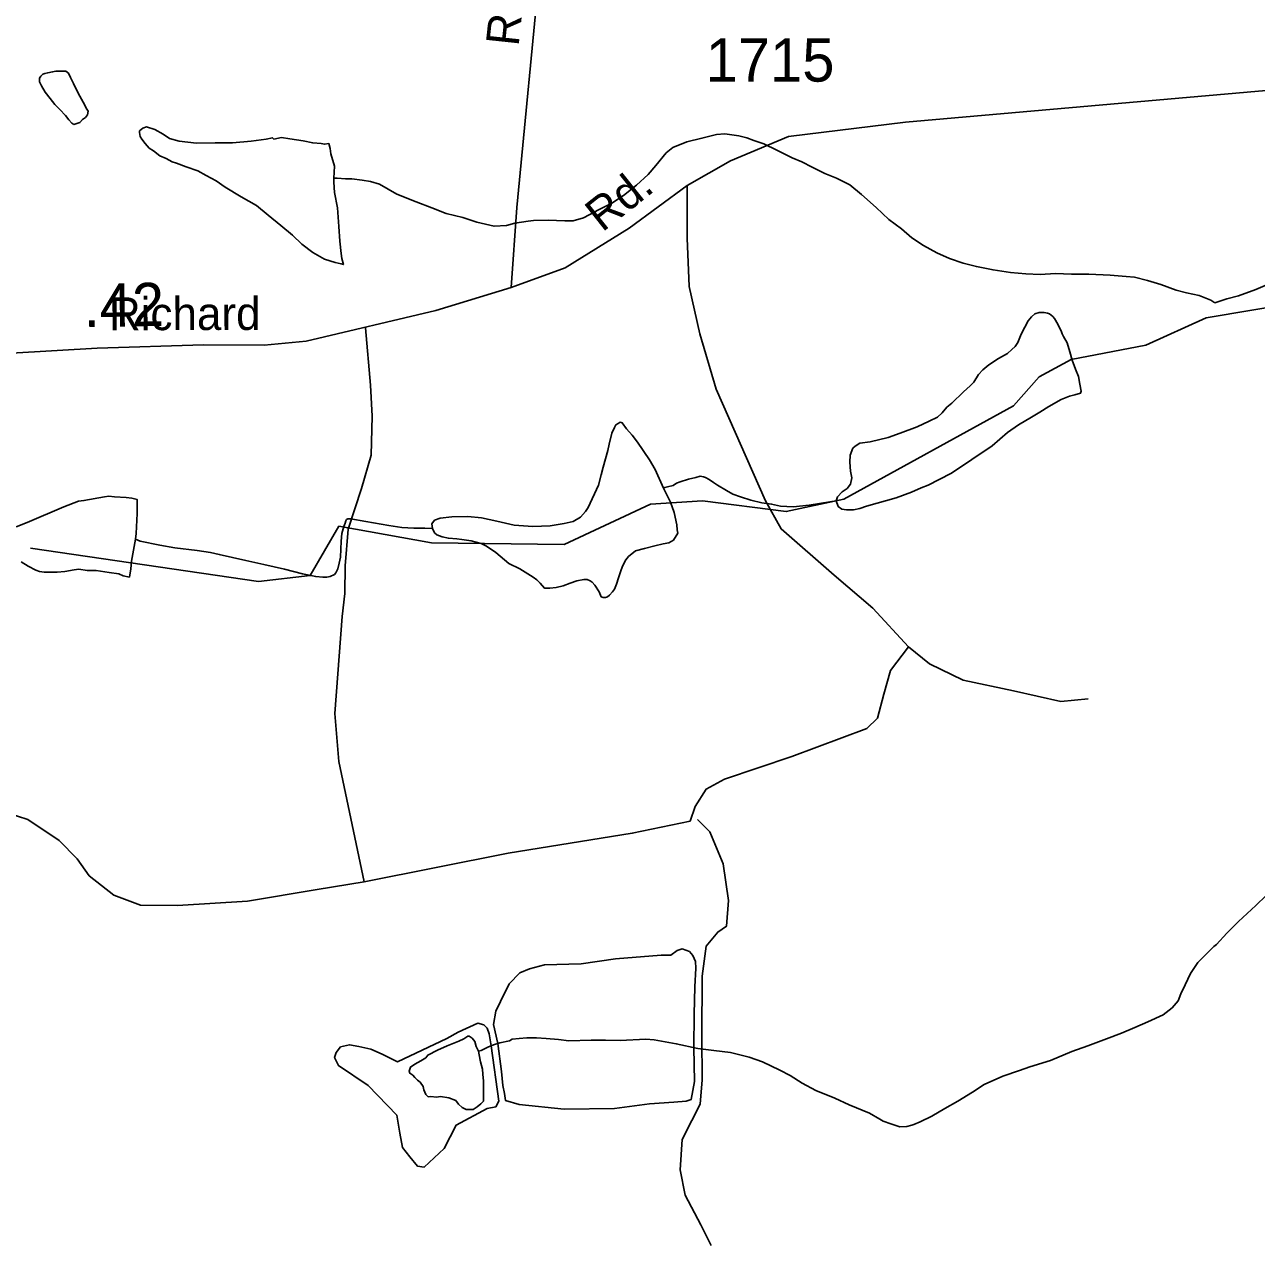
# Model space of a CAD drawing. Extents: x 2126262 to 2293712, y 749403 to 919119.
# Drawn here: x 2190988 to 2194544, y 799144 to 802665 of the extents above; entities that cross this region are included whole.
import ezdxf

# ---------------------------------------------------------------- set-up
doc = ezdxf.new("R2010")
doc.units = 0
for name, color, linetype in [('Exist Hydrographic Misc Water Feature', 7, 'Continuous'), ('Exist Hydrographic Pond Under 1500 Sq Ft', 7, 'Continuous'), ('Exist Road Non-System Type 51', 7, 'Continuous'), ('Exist Road Secondary Mileage Hundredths English Label', 7, 'Continuous'), ('Exist Road Secondary Type 51 Attributed', 7, 'Continuous'), ('Exist Road Secondary Type 51 Label', 7, 'Continuous'), ('Exist Road Secondary Type 51 Number Label', 7, 'Continuous')]:
    doc.layers.add(name, color=color, linetype=linetype)

msp = doc.modelspace()

# ---------------------------------------------------------------- linework, layer by layer
at = {"layer": 'Exist Hydrographic Misc Water Feature'}
for points in [[(2191129.8, 802376.3), (2191147.4, 802382.4), (2191155.4, 802390.5), (2191163.4, 802396.6), (2191169.5, 802404.6), (2191171.6, 802414.6), (2191167.3, 802420.6), (2191157.2, 802440.5), (2191147, 802458.5), (2191139, 802474.4), (2191128.7, 802494.3), (2191120.7, 802512.2), (2191114.8, 802524.2), (2191106.6, 802530.1), (2191092.4, 802530.1), (2191078.5, 802529.9), (2191068.7, 802527.9), (2191054.7, 802525.8), (2191046.7, 802523.8), (2191040.8, 802521.7), (2191034.8, 802515.6), (2191030.7, 802509.6), (2191030.7, 802499.6), (2191037.1, 802487.7), (2191046.9, 802469.7), (2191061.3, 802451.8), (2191075.2, 802434), (2191089.6, 802420.1), (2191105.6, 802402.2), (2191115.4, 802390.2), (2191123.8, 802380.3), (2191129.8, 802376.3)], [(2191880.5, 802221.6), (2191880.5, 802209.6), (2191882.7, 802179.6), (2191890.9, 802135.7), (2191895.4, 802081.7), (2191897.7, 802039.7), (2191902, 802003.8), (2191904, 801989.8), (2191908.1, 801971.8), (2191902.2, 801973.8), (2191884.1, 801977.7), (2191854, 801987.5), (2191820, 802007.2), (2191787.8, 802031), (2191761.7, 802056.8), (2191727.5, 802084.5), (2191691.2, 802114.3), (2191657, 802142.1), (2191613.1, 802167.7), (2191566.7, 802195.4), (2191540.7, 802213.3), (2191512.4, 802229), (2191488.4, 802242.9), (2191454.6, 802254.6), (2191426.3, 802264.4), (2191414.2, 802268.3), (2191396.3, 802278.2), (2191378.3, 802286.1), (2191360, 802300), (2191347.9, 802307.9), (2191336, 802321.7), (2191326, 802333.7), (2191321.7, 802341.7), (2191319.6, 802353.6), (2191319.6, 802357.6), (2191329.7, 802365.8), (2191339.7, 802369.8), (2191363.7, 802361.9), (2191387.7, 802348.1), (2191405.8, 802336.3), (2191434.1, 802328.5), (2191484.1, 802322.8), (2191538, 802323.2), (2191588.1, 802323.5), (2191641.8, 802327.9), (2191685.7, 802334.2), (2191703.7, 802338.3), (2191707.8, 802334.3), (2191729.7, 802338.5), (2191753.7, 802334.7), (2191791.7, 802329), (2191819.8, 802323.1), (2191843.8, 802321.3), (2191853.8, 802319.3), (2191865.7, 802321.4), (2191870, 802307.4), (2191872.1, 802291.5), (2191882.3, 802255.6), (2191880.5, 802221.6)], [(2191880.5, 802221.6), (2191890.5, 802221.6), (2191914.5, 802219.8), (2191932.5, 802219.9), (2191962.5, 802216.1), (2191986.5, 802212.3), (2192012.5, 802204.5), (2192062.8, 802174.8), (2192118.7, 802153.2), (2192163, 802135.6), (2192205.1, 802119.8), (2192253.2, 802108.2), (2192293.2, 802094.4), (2192343.3, 802082.8), (2192379.1, 802085.1), (2192403.1, 802091.2), (2192441.3, 802097.5), (2192457.3, 802099.6), (2192498.9, 802099.9), (2192547.1, 802098.2), (2192571.1, 802098.4), (2192601, 802106.6), (2192646.7, 802130.9), (2192682.8, 802149.1), (2192716.5, 802171.3), (2192754.2, 802201.6), (2192788, 802231.8), (2192810, 802258), (2192839.7, 802294.2), (2192859.6, 802310.3), (2192899.6, 802326.6), (2192943.2, 802336.8), (2192985.3, 802347.2), (2193009.3, 802349.3), (2193049.3, 802343.6), (2193073.2, 802337.8), (2193093.1, 802329.9), (2193121.4, 802320.1), (2193159.6, 802302.3), (2193203.7, 802280.6), (2193231.8, 802268.9), (2193261.7, 802253.1), (2193298, 802235.3), (2193332, 802221.6), (2193370, 802201.8), (2193404.2, 802174.1), (2193446.4, 802136.4), (2193482.7, 802102.6), (2193519, 802074.9), (2193549, 802049.1), (2193583.2, 802027.4), (2193621.6, 802005.7), (2193657.4, 801989.9), (2193697.4, 801976.1), (2193735.6, 801966.4), (2193783.8, 801956.8), (2193833.8, 801949.2), (2193877.7, 801945.4), (2193919.7, 801943.7), (2193963.8, 801946), (2194009.7, 801944.3), (2194059.8, 801944.7), (2194121.7, 801941.1), (2194167.8, 801937.4), (2194191.8, 801935.6), (2194229.7, 801925.8), (2194267.7, 801914.2), (2194312, 801898.4), (2194341.9, 801890.7), (2194378, 801882.9), (2194412, 801869.1), (2194423.9, 801861.2)], [(2194423.9, 801861.2), (2194458, 801873.4), (2194492, 801881.7), (2194541.8, 801900.1), (2194575.7, 801914.2), (2194599.4, 801924.4), (2194649.5, 801934.7), (2194677.6, 801939), (2194715.5, 801941.2), (2194777.4, 801929.7), (2194821.5, 801917.9), (2194853.7, 801906.2), (2194885.7, 801892.4), (2194919.9, 801870.7), (2194962, 801836.9), (2194990.3, 801809.2), (2195008.5, 801787.3), (2195012.4, 801781.3)], [(2191004.5, 801153.3), (2191663.5, 801057.6), (2191812.6, 801074.3), (2191895.4, 801216.9), (2192162.6, 801168.8), (2192545.4, 801164.1), (2192794.6, 801280.4), (2192944.5, 801290.4), (2193186.4, 801259.2), (2193352.5, 801295.1), (2193842.6, 801563.9), (2193916.4, 801647.6), (2194008.5, 801698.3), (2194224.6, 801739.7), (2194398.5, 801818.1), (2194656.5, 801862)], [(2193330.4, 801289.9), (2193334.3, 801301.9), (2193348.2, 801316), (2193362.2, 801326.1), (2193372, 801338.2), (2193375.9, 801356.2), (2193371.8, 801376.1), (2193369.8, 801402.1), (2193371.4, 801422.1), (2193379.2, 801442.1), (2193385.1, 801448.2), (2193399.3, 801456.3), (2193429.2, 801460.5), (2193480.9, 801472.8), (2193514.9, 801485.1), (2193564.8, 801503.4), (2193598.8, 801519.6), (2193622.8, 801531.8), (2193636.5, 801543.9), (2193650.5, 801560), (2193664.2, 801572.1), (2193698, 801604.3), (2193717.9, 801622.5), (2193728, 801632.5), (2193741.7, 801654.6), (2193753.8, 801668.7), (2193771.4, 801682.7), (2193799.5, 801700.9), (2193825.2, 801715.1), (2193837.3, 801727.2), (2193847.3, 801735.3), (2193854.9, 801747.3), (2193865, 801771.4), (2193874.8, 801791.5), (2193884.6, 801809.5), (2193894.5, 801821.6), (2193904.5, 801829.7), (2193916.4, 801833.7), (2193930.6, 801833.8), (2193940.4, 801831.9), (2193946.6, 801830), (2193956.4, 801822), (2193960.5, 801816), (2193970.8, 801800.1), (2193980.8, 801778.2), (2193982.7, 801772.2), (2193987, 801764.2)], [(2193987, 801764.2), (2193997, 801746.3), (2194005.2, 801720.4), (2194011.6, 801696.4), (2194021.4, 801670.5), (2194029.8, 801648.6), (2194033.7, 801626.6), (2194038, 801606.6), (2194036, 801600.6), (2194020, 801596.5), (2194004, 801592.4), (2193980.2, 801582.3), (2193944.3, 801562), (2193918.5, 801545.8), (2193894.5, 801531.6), (2193856.8, 801509.4), (2193825, 801487.2), (2193781.3, 801448.9), (2193663.8, 801370.1), (2193627.9, 801351.9), (2193595.9, 801335.7), (2193576, 801327.5), (2193548.1, 801315.3), (2193504.3, 801299.1), (2193418.6, 801274.4), (2193398.5, 801268.3), (2193380.4, 801264.2), (2193360.5, 801264.1), (2193346.6, 801266), (2193336.5, 801273.9), (2193330.4, 801289.9)], [(2192165.3, 801209.8), (2192163.2, 801223.8), (2192171.2, 801233.9), (2192187.2, 801240), (2192221.1, 801244.2), (2192267, 801244.6), (2192307, 801240.8), (2192351.3, 801231.1), (2192401.3, 801219.5), (2192455.2, 801215.9), (2192505.3, 801218.2), (2192545, 801224.5), (2192571.1, 801230.6), (2192593, 801242.8), (2192606.8, 801258.9), (2192614.8, 801271), (2192644.3, 801335.1), (2192652.1, 801365.2), (2192658, 801387.2), (2192671.8, 801435.3), (2192675.4, 801453.3), (2192683.2, 801485.3), (2192691.2, 801501.4), (2192694.9, 801509.4), (2192701.1, 801513.4), (2192707, 801517.5), (2192713, 801515.5), (2192725.3, 801497.6), (2192741.3, 801479.7), (2192757.5, 801459.9), (2192791.7, 801408.1), (2192807.9, 801380.2), (2192832.3, 801326.4)], [(2192832.3, 801326.4), (2192836.2, 801328.4), (2192844.2, 801330.5), (2192860.2, 801334.6), (2192870.2, 801340.7), (2192880.3, 801344.8), (2192904.1, 801352.9), (2192926, 801357.1), (2192937.9, 801361.1), (2192948, 801359.2), (2192953.9, 801357.3), (2192964, 801351.3), (2192976.3, 801343.4), (2192988.2, 801335.5), (2193014.2, 801319.7), (2193032.2, 801309.8), (2193054.4, 801302), (2193084.5, 801292.2), (2193116.5, 801284.4), (2193144.4, 801280.6), (2193170.4, 801274.7), (2193206.5, 801273), (2193252.5, 801277.3), (2193288.6, 801283.6), (2193330.4, 801289.9)], [(2192832.3, 801326.4), (2192852.4, 801286.6), (2192862.7, 801256.7), (2192871.1, 801220.7), (2192871.3, 801206.7), (2192873.3, 801196.8), (2192861.2, 801176.7), (2192847.5, 801168.6), (2192831.5, 801166.4), (2192807.5, 801160.3), (2192777.6, 801152.1), (2192751.5, 801145.9), (2192731.6, 801129.8), (2192723.6, 801119.7), (2192714, 801101.7), (2192708, 801085.6), (2192702.3, 801067.6), (2192696.2, 801049.5), (2192690.4, 801035.5), (2192684.5, 801027.5), (2192676.5, 801017.5), (2192670.5, 801013.4), (2192664.6, 801011.4), (2192658.4, 801011.3), (2192652.5, 801013.3), (2192646.5, 801027.2), (2192634.2, 801047.1), (2192626.2, 801055.1), (2192620.3, 801059.1), (2192612.3, 801063), (2192602.2, 801062.9), (2192582.1, 801058.8), (2192562.3, 801052.6), (2192542.2, 801044.5), (2192522.5, 801040.4), (2192504.4, 801038.3), (2192488.4, 801038.1), (2192476.1, 801052.1), (2192466.3, 801062), (2192456.2, 801070), (2192417.9, 801093.6), (2192385.9, 801109.4), (2192347.8, 801141.1), (2192321.7, 801158.9), (2192305.5, 801166.8), (2192277.4, 801174.6), (2192249.6, 801178.4), (2192235.4, 801180.4), (2192211.4, 801182.2), (2192193.6, 801186.1), (2192177.6, 801192), (2192171.4, 801197.9), (2192165.3, 801209.8)], [(2190963.7, 801215.5), (2190995.5, 801227.8), (2191101.3, 801272.5), (2191143.3, 801288.8), (2191159.3, 801290.8), (2191219, 801301.3), (2191231.1, 801303.4), (2191247.1, 801301.5), (2191280.9, 801299.8), (2191297.1, 801297.9), (2191313.1, 801293.9), (2191313.3, 801254), (2191309.8, 801196), (2191307.7, 801179.9)], [(2191307.7, 801179.9), (2191321.9, 801174.1), (2191378.1, 801162.4), (2191422, 801154.7), (2191485.9, 801147.2), (2191524.1, 801141.4), (2191549.9, 801135.6), (2191626.2, 801118.2), (2191678.3, 801106.6), (2191738.2, 801092.9), (2191790.4, 801079.3), (2191828.6, 801071.5), (2191848.5, 801069.7), (2191860.6, 801069.8), (2191870.4, 801071.8), (2191882.3, 801077.9), (2191886.2, 801082), (2191892.1, 801094), (2191896.2, 801110), (2191899.9, 801128), (2191901.8, 801174.1), (2191903.4, 801196.1), (2191909.6, 801216.1), (2191913.3, 801226.1), (2191915.3, 801232.1), (2191917.2, 801236.1), (2191921.3, 801238.2), (2191925.2, 801238.2), (2191929.3, 801238.2), (2191973.1, 801230.5), (2192039.2, 801219), (2192077.3, 801213.2), (2192111.1, 801211.5), (2192143.1, 801211.7), (2192165.3, 801209.8)], [(2191307.7, 801179.9), (2191296.3, 801115.9), (2191294.4, 801093.8), (2191290.5, 801069.8), (2191272.5, 801073.7), (2191260.4, 801079.7), (2191232.5, 801083.5), (2191194.6, 801089.2), (2191168.5, 801089.1), (2191144.5, 801092.9), (2191130.6, 801090.7), (2191104.5, 801086.6), (2191082.4, 801084.4), (2191060.5, 801084.3), (2191044.5, 801084.2), (2191030.5, 801086), (2191020.5, 801090), (2190998.5, 801101.8), (2190978.4, 801113.7)], [(2192297.7, 799701.2), (2192305.7, 799703.3), (2192325.4, 799713.4), (2192341.4, 799719.5), (2192359.5, 799725.7), (2192387.6, 799731.8), (2192395.5, 799735.9), (2192415.4, 799738), (2192437.4, 799740.2), (2192465.3, 799740.4), (2192493.2, 799738.6), (2192529.4, 799734.9), (2192559.4, 799731.1), (2192623.2, 799733.5), (2192665.2, 799733.8), (2192707.2, 799732), (2192781.3, 799736.5), (2192805.2, 799734.8), (2192869.2, 799723.2), (2192931.6, 799709.6), (2192977.5, 799703.9), (2193025.5, 799698.3), (2193079.4, 799684.7), (2193117.7, 799670.9), (2193167.8, 799647.3), (2193197.9, 799631.5), (2193232, 799609.7), (2193272.1, 799588), (2193326.3, 799566.4), (2193368.5, 799546.7), (2193426.6, 799523.1), (2193456.7, 799505.3), (2193466.7, 799499.4), (2193488.7, 799491.6), (2193514.7, 799483.7), (2193534.8, 799483.9), (2193548.8, 799487.9), (2193554.7, 799490), (2193572.8, 799498.1), (2193606.4, 799514.4), (2193644.5, 799536.6), (2193682.3, 799556.9), (2193723.9, 799583.1), (2193757.7, 799605.4), (2193811.6, 799629.7), (2193859.4, 799646.1), (2193889.6, 799656.2), (2193949.2, 799674.7), (2194010.9, 799701.1), (2194056.9, 799717.4), (2194110.8, 799737.7), (2194154.7, 799754.1), (2194192.4, 799770.3), (2194230.6, 799786.6), (2194274.2, 799806.9), (2194300.3, 799827), (2194317.9, 799847.1), (2194325.7, 799867.2), (2194337.8, 799893.3), (2194353.4, 799925.4), (2194375.1, 799957.5), (2194421.1, 800003.8), (2194428.6, 800009.9), (2194458.4, 800042.1), (2194492.4, 800076.3), (2194542, 800122.6), (2194571.8, 800150.8)], [(2192297.7, 799701.2), (2192299.8, 799691.3), (2192303.9, 799671.3), (2192310, 799649.4), (2192310.2, 799635.4), (2192312.3, 799615.4), (2192312.5, 799597.4), (2192312.5, 799583.4), (2192312.7, 799565.4), (2192312.7, 799557.4), (2192304.7, 799549.3), (2192294.7, 799541.3), (2192282.8, 799533.2), (2192276.6, 799533.1), (2192262.7, 799533), (2192250.8, 799539), (2192240.7, 799548.9), (2192232.7, 799558.9), (2192212.6, 799566.7), (2192188.7, 799570.6), (2192176.8, 799568.5), (2192160.8, 799570.4), (2192152.8, 799570.3), (2192146.4, 799576.2), (2192140.5, 799590.2), (2192138.4, 799600.1), (2192130.2, 799612.1), (2192122.2, 799618), (2192114.2, 799626), (2192108.3, 799632), (2192100.3, 799637.9), (2192098.2, 799643.9), (2192101.9, 799655.9), (2192114, 799664), (2192132.1, 799674.1), (2192146, 799682.2), (2192151.7, 799690.2), (2192179.6, 799704.4), (2192207.5, 799716.6), (2192241.6, 799730.9), (2192255.5, 799737), (2192267.4, 799745.1), (2192271.5, 799745.1), (2192279.5, 799739.1), (2192287.5, 799729.2), (2192291.4, 799715.2), (2192297.7, 799701.2)]]:
    msp.add_lwpolyline(points, dxfattribs=at)
at = {"layer": 'Exist Hydrographic Pond Under 1500 Sq Ft'}
for points in [[(2192353.6, 799723.7), (2192365, 799642.7), (2192368.7, 799602.4), (2192373.6, 799579.1), (2192376, 799559.6), (2192415.1, 799547.4), (2192545.7, 799534.7), (2192691, 799536.4), (2192791.5, 799549.6), (2192862, 799554.7), (2192897.4, 799557.1), (2192912, 799562), (2192921.8, 799614.6), (2192919.8, 799712.1), (2192920.6, 799808.8), (2192923, 799887), (2192925.4, 799940.8), (2192924.2, 799960.3), (2192916.9, 799977.4), (2192907.1, 799989.6), (2192886.4, 799997), (2192871.7, 799992.1), (2192853.4, 799978.6), (2192825.3, 799978.6), (2192693.3, 799968.6), (2192594.6, 799954.2), (2192488.9, 799950.4), (2192445.6, 799939.6), (2192417.5, 799927.3), (2192387, 799895.6), (2192361.3, 799845.5), (2192347.9, 799817.4), (2192341.8, 799778.3), (2192353.6, 799723.7)], [(2192334.3, 799716.8), (2192329.4, 799751.9), (2192323.1, 799767.8), (2192313.6, 799777.3), (2192296.2, 799782.1), (2192239.1, 799756.7), (2192206.9, 799738.4), (2192064.8, 799671.3), (2192020.5, 799693.3), (2191987.3, 799707.6), (2191952.4, 799715.5), (2191925.5, 799720.2), (2191900.1, 799713.9), (2191887.5, 799698), (2191882.7, 799683.8), (2191893.8, 799660), (2191979.3, 799602.9), (2192062.5, 799516.6), (2192071.2, 799465), (2192079.1, 799423.8), (2192099.7, 799396.9), (2192121.9, 799369.9), (2192140.9, 799366.8), (2192199.5, 799420.6), (2192234.1, 799488.2), (2192323.1, 799536.4), (2192348.4, 799541.1), (2192356.4, 799557), (2192334.3, 799716.8)]]:
    msp.add_lwpolyline(points, dxfattribs=at)
at = {"layer": 'Exist Road Non-System Type 51'}
for points in [[(2192900.3, 802199.9), (2192900.9, 802048.5), (2192906.5, 801908.8), (2192937.2, 801771.9), (2192984.6, 801612.7), (2193126.9, 801290.2), (2193171.5, 801209.2), (2193325, 801075.2), (2193436.7, 800980.2), (2193539.9, 800868.5)], [(2191971.7, 801789.3), (2191986, 801623.5), (2191991.6, 801534.1), (2191988.1, 801421.7), (2191960.2, 801325.3), (2191921.9, 801208.7), (2191913.5, 801102.6), (2191912.1, 801022.9), (2191905.1, 800955.9), (2191883.5, 800675.9), (2191894.6, 800537.6), (2191967.9, 800190.6)], [(2193539.9, 800868.5), (2193487.6, 800800.7), (2193468.1, 800732.3), (2193449.9, 800662.5), (2193419.2, 800633.1), (2193202.9, 800552.1), (2193008.3, 800487.2), (2192955.3, 800457.9), (2192923.2, 800407.6), (2192909.2, 800365.7)], [(2193539.9, 800868.5), (2193599.9, 800819.6), (2193697.6, 800772.1), (2193842.7, 800741.4), (2193979.5, 800710.7), (2194057.6, 800719)], [(2190231.2, 800441.7), (2190291.7, 800451.8), (2190323.8, 800442), (2190399.2, 800400.1), (2190464.8, 800349.8), (2190509.4, 800348.4), (2190657.4, 800379.2), (2190774.6, 800384.8), (2190937.2, 800389.6), (2190997.2, 800370.1), (2191087.9, 800310), (2191139.5, 800257), (2191174.4, 800208.1), (2191245.6, 800152.2), (2191322.3, 800122.9), (2191429.1, 800122.2), (2191631.4, 800134.7), (2191832.4, 800168.3), (2191967.9, 800190.6)], [(2191967.9, 800190.6), (2192383.8, 800272.8), (2192741.8, 800330.8), (2192909.2, 800365.7)], [(2192930.1, 800369.9), (2192966.4, 800335), (2193004.1, 800242.8), (2193019.4, 800136.6), (2193013.8, 800062.1), (2192988.7, 800045.4), (2192955.2, 800004.9), (2192944, 799918.3), (2192942.7, 799743.7), (2192943.4, 799618.7), (2192937.8, 799548.9), (2192914, 799501.4), (2192886.1, 799446.9), (2192879.9, 799359.6), (2192895.2, 799285.6), (2192939.9, 799200.4), (2192969.7, 799140.3)]]:
    msp.add_lwpolyline(points, dxfattribs=at)
at = {"layer": 'Exist Road Secondary Type 51 Attributed'}
for points in [[(2190178.8, 804695.1), (2190595.6, 804837.5), (2190760.9, 804927.6), (2191091, 805172.7), (2191323.3, 805357.8), (2191405.6, 805392.7), (2191494.2, 805418.5), (2191999.4, 805452), (2192198.9, 805475.8), (2192327.3, 805477.2), (2192421.5, 805463.9), (2192523.3, 805427.6), (2192598.7, 805360.6), (2192655.9, 805292.1), (2192709.6, 805168.5), (2192710.3, 805070.1), (2192697.8, 804835.4), (2192637.8, 804282.4), (2192607.1, 804025.4), (2192573.6, 803757.3), (2192477.3, 802848.1), (2192408.9, 802137.2), (2192392, 801905.5)], [(2192392, 801905.5), (2192548.6, 801962.5), (2192732.8, 802077), (2192900.3, 802199.9), (2193025.4, 802271.6), (2193192.9, 802341.4), (2193530.5, 802383.3), (2194824.1, 802496.4)], [(2190207.7, 801672.9), (2191197.2, 801730.6), (2191504.2, 801740.4), (2191679.3, 801739.7), (2191800.7, 801750.9), (2192175.4, 801839.6), (2192392, 801905.5)]]:
    msp.add_lwpolyline(points, dxfattribs=at)

# ---------------------------------------------------------------- texts
at = {"layer": 'Exist Road Secondary Mileage Hundredths English Label'}
msp.add_text('.42', height=125, rotation=0.8737, dxfattribs=at).set_placement((2191159.1, 801791.5))
at = {"layer": 'Exist Road Secondary Type 51 Label'}
for s, rotation, p in [('Robbins', 83.9393, (2192413.7, 802600.3)), ('Rd.', 38.4704, (2192655.3, 802063.7)), ('Richard', 0.1675, (2191231.4, 801782.3))]:
    msp.add_text(s, height=95, rotation=rotation, dxfattribs=at).set_placement(p)
at = {"layer": 'Exist Road Secondary Type 51 Number Label'}
msp.add_text('1715', height=125, dxfattribs=at).set_placement((2192953.9, 802500.1))

doc.saveas('drawing.dxf')
